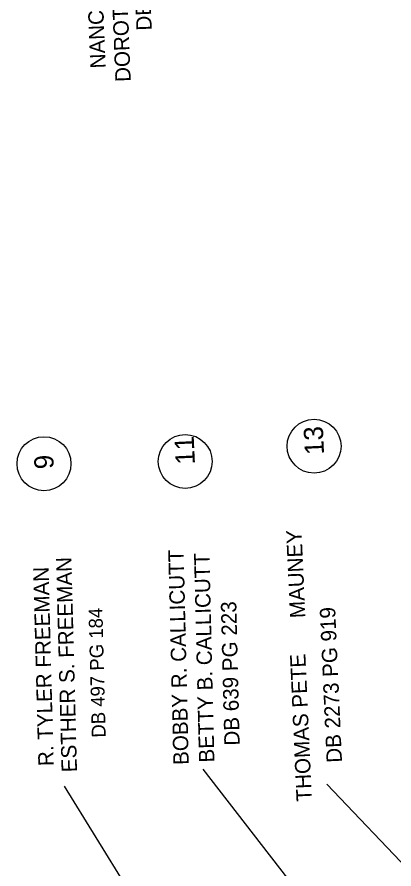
# Model space of a CAD drawing. Extents: x 1627482 to 1629573, y 760826 to 766301.
# Drawn here: x 1628135.3 to 1628257.6, y 762438.3 to 762714.8 of the extents above; entities that cross this region are included whole.
import ezdxf

# ---------------------------------------------------------------- set-up
doc = ezdxf.new("R2010")
doc.units = 0
for name, color, linetype in [('Exist Property Deed Book Text', 7, 'Continuous'), ('Exist Property Line Leader', 7, 'Continuous'), ('Exist Property Owner Number CELL', 7, 'Continuous'), ('Exist Property Owner Text', 7, 'Continuous')]:
    doc.layers.add(name, color=color, linetype=linetype)

msp = doc.modelspace()

# ---------------------------------------------------------------- linework, layer by layer
at = {"layer": 'Exist Property Line Leader'}
for p, q in [((1628311.87, 762320.85), (1628195.75, 762470.72)), ((1628310.11, 762387.88), (1628235.82, 762465.89)), ((1628295.06, 762230.9), (1628150.72, 762465.19))]:
    msp.add_line(p, q, dxfattribs=at)
at = {"layer": 'Exist Property Owner Number CELL'}
for centre in [(1628231.7, 762575.52), (1628189.88, 762570.57), (1628189.88, 762570.57), (1628189.88, 762570.57), (1628144.03, 762569.84), (1628144.03, 762569.84), (1628144.03, 762569.84)]:
    msp.add_circle(centre, 8.75, dxfattribs=at)

# ---------------------------------------------------------------- texts
at = {"layer": 'Exist Property Deed Book Text'}
for s, height, rotation, p in [('DB 2223 PG 2248', 5, 92.2582, (1628179.04, 762710.47)), ('DB 639 PG 223', 5, 91.377, (1628207.56, 762478.43)), ('DB 497 PG 184', 4.5, 91.5017, (1628164.08, 762481.01)), ('DB 2273 PG 919', 5, 92.5763, (1628240.79, 762472.93))]:
    msp.add_text(s, height=height, rotation=rotation, dxfattribs=at).set_placement(p)
at = {"layer": 'Exist Property Owner Number CELL'}
for s, p in [('13', (1628234.96, 762572.86)), ('11', (1628193.05, 762569.69)), ('11', (1628193.05, 762569.69)), ('11', (1628193.05, 762569.69)), ('9', (1628147.24, 762568.22)), ('9', (1628147.24, 762568.22)), ('9', (1628147.24, 762568.22))]:
    msp.add_text(s, height=6.25, rotation=92.6915, dxfattribs=at).set_placement(p)
at = {"layer": 'Exist Property Owner Text'}
for s, rotation, p in [('DOROTHY CAROL TOWNSEND', 92.2582, (1628172.21, 762693.82)), ('NANCY HAYNES MOTLEY', 92.2582, (1628164.07, 762698.19)), ('MAUNEY', 92.5763, (1628228.9, 762519.85)), ('BOBBY R. CALLICUTT', 91.377, (1628191.04, 762472.17)), ('BETTY B. CALLICUTT', 91.377, (1628199.36, 762472.94)), ('ESTHER S. FREEMAN', 91.5017, (1628154.76, 762469.79)), ('R. TYLER FREEMAN', 91.5017, (1628147.2, 762471.8)), ('THOMAS PETE', 92.5763, (1628231.02, 762460.37))]:
    msp.add_text(s, height=5, rotation=rotation, dxfattribs=at).set_placement(p)

doc.saveas('drawing.dxf')
